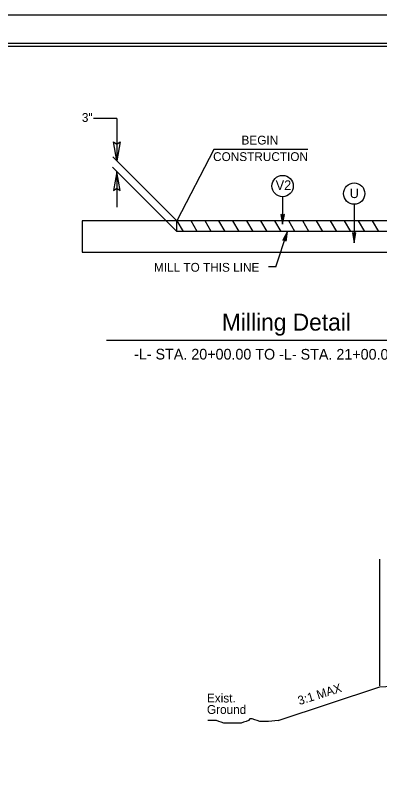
# Model space of a CAD drawing. Extents: x 1497225 to 1499181, y 579958 to 582278.
# Drawn here: x 1497879 to 1498169, y 581678 to 582278 of the extents above; entities that cross this region are included whole.
import ezdxf

# ---------------------------------------------------------------- set-up
doc = ezdxf.new("R2010")
doc.units = 0
for name, color, linetype in [('Default', 7, 'Continuous'), ('Old_Level_1', 7, 'Continuous'), ('Prop Dimension', 7, 'Continuous'), ('Prop Dimension Text', 7, 'Continuous'), ('Prop EOT', 7, 'Continuous'), ('Sheet Cutting Line CELL', 7, 'Continuous'), ('Sheet Plot Border Inside CELL', 7, 'Continuous'), ('Sheet Plot Border Outside CELL', 7, 'Continuous'), ('Sheet Typical CELL', 7, 'Continuous'), ('Typical ID Circle CELL', 7, 'Continuous'), ('Typical Terminator CELL', 7, 'Continuous'), ('Typical Text General CELL', 7, 'Continuous'), ('Typical Text ID Circle CELL', 7, 'Continuous')]:
    doc.layers.add(name, color=color, linetype=linetype)

msp = doc.modelspace()

# ---------------------------------------------------------------- linework, layer by layer
at = {"layer": 'Default'}
for p, q in [((1497959.55, 582195.79), (1497940.95, 582195.79)), ((1497959.55, 582195.79), (1497959.55, 582162.11)), ((1497956.44, 582165.21), (1498007.12, 582114.53)), ((1497956.05, 582157), (1498007.12, 582105.93)), ((1497959.55, 582153.51), (1497959.55, 582125.41))]:
    msp.add_line(p, q, dxfattribs=at)
at = {"layer": 'Old_Level_1'}
for p, q in [((1498036.44, 582171.24), (1498007.12, 582114.53)), ((1498111.16, 582171.24), (1498036.44, 582171.24)), ((1498085.75, 582077.93), (1498095.17, 582105.93)), ((1498085.75, 582077.93), (1498079.88, 582077.93)), ((1497951.27, 582019.56), (1498227.27, 582019.56)), ((1498168.53, 581744.91), (1498168.53, 581845.55)), ((1498168.53, 581744.13), (1498216.42, 581746.79)), ((1498087.75, 581717.2), (1498168.53, 581744.13))]:
    msp.add_line(p, q, dxfattribs=at)
msp.add_lwpolyline([(1498087.75, 581717.2), (1498079.88, 581716.55), (1498077.91, 581716.55), (1498074.96, 581716.55), (1498072.99, 581716.55), (1498071.02, 581717.2), (1498069.06, 581717.86), (1498067.09, 581718.52), (1498065.12, 581718.52), (1498064.14, 581717.2), (1498062.17, 581716.55), (1498060.2, 581715.89), (1498058.24, 581715.24), (1498056.27, 581715.24), (1498054.3, 581715.24), (1498052.34, 581715.24), (1498050.37, 581715.24), (1498048.4, 581715.24), (1498046.44, 581715.24), (1498044.47, 581715.24), (1498042.5, 581715.89), (1498040.54, 581716.55), (1498038.57, 581717.2), (1498035.61, 581717.2), (1498033.65, 581717.2), (1498031.68, 581717.2)], dxfattribs=at)
at = {"layer": 'Prop Dimension'}
msp.add_lwpolyline([(1498285.68, 582114.53), (1497932.02, 582114.53), (1497932.02, 582089.48), (1498279.23, 582089.48)], dxfattribs=at)
at = {"layer": 'Prop EOT'}
for p, q in [((1498285.68, 582114.53), (1498007.12, 582114.53)), ((1498007.12, 582105.93), (1498007.12, 582114.53)), ((1498012.36, 582105.93), (1498007.4, 582114.53)), ((1498023.45, 582105.93), (1498018.48, 582114.53)), ((1498034.53, 582105.93), (1498029.57, 582114.53)), ((1498045.62, 582105.93), (1498040.65, 582114.53)), ((1498056.7, 582105.93), (1498051.74, 582114.53)), ((1498067.79, 582105.93), (1498062.82, 582114.53)), ((1498078.87, 582105.93), (1498073.91, 582114.53)), ((1498089.96, 582105.93), (1498084.99, 582114.53)), ((1498101.04, 582105.93), (1498096.08, 582114.53)), ((1498112.13, 582105.93), (1498107.16, 582114.53)), ((1498123.21, 582105.93), (1498118.25, 582114.53)), ((1498134.3, 582105.93), (1498129.33, 582114.53)), ((1498145.38, 582105.93), (1498140.42, 582114.53)), ((1498156.47, 582105.93), (1498151.5, 582114.53)), ((1498167.55, 582105.93), (1498162.59, 582114.53)), ((1498284.72, 582105.93), (1498007.12, 582105.93))]:
    msp.add_line(p, q, dxfattribs=at)
at = {"layer": 'Sheet Cutting Line CELL'}
msp.add_line((1498909.23, 582277.96), (1497225.23, 582277.96), dxfattribs=at)
at = {"layer": 'Sheet Plot Border Inside CELL'}
msp.add_lwpolyline([(1498904.73, 582255.51), (1497238.23, 582255.51), (1497238.23, 581200.41), (1498904.73, 581200.41)], close=True, dxfattribs=at)
at = {"layer": 'Sheet Plot Border Outside CELL'}
msp.add_lwpolyline([(1498909.23, 582277.96), (1497225.23, 582277.96), (1497225.23, 581177.96), (1498909.23, 581177.96)], close=True, dxfattribs=at)
at = {"layer": 'Sheet Typical CELL'}
msp.add_lwpolyline([(1498892.23, 582252.96), (1497392.23, 582252.96), (1497392.23, 581202.96), (1498892.23, 581202.96)], close=True, dxfattribs=at)
at = {"layer": 'Typical ID Circle CELL'}
for p, q in [((1498091.22, 582133.6), (1498091.22, 582111.73)), ((1498148.09, 582127.64), (1498148.09, 582097.07))]:
    msp.add_line(p, q, dxfattribs=at)
for centre in [(1498091.22, 582142.06), (1498148.09, 582136.1)]:
    msp.add_circle(centre, 8.46, dxfattribs=at)
at = {"layer": 'Typical Terminator CELL'}
for points in [[(1497962.13, 582177.1), (1497959.55, 582162.11), (1497956.88, 582177.19), (1497959.55, 582175.27)], [(1497962.13, 582138.51), (1497959.55, 582153.51), (1497956.88, 582138.43), (1497959.55, 582140.34)], [(1498089.89, 582119.46), (1498091.22, 582111.73), (1498092.6, 582119.51), (1498091.22, 582118.52)], [(1498093.97, 582098.17), (1498095.17, 582105.93), (1498091.39, 582099), (1498093.01, 582099.5)], [(1498146.76, 582104.81), (1498148.09, 582097.07), (1498149.46, 582104.85), (1498148.09, 582103.86)]]:
    msp.add_lwpolyline(points, close=True, dxfattribs=at)

# ---------------------------------------------------------------- texts
at = {"layer": 'Old_Level_1'}
for s, p in [('3"', (1497931.71, 582193.07)), ('MILL TO THIS LINE', (1497988.98, 582073.99))]:
    msp.add_text(s, height=7, dxfattribs=at).set_placement(p)
for s, height, rotation, p in [('-L- STA. 20+00.00 TO -L- STA. 21+00.00', 8.5, 359.94924, (1497973.18, 582004.26)), ('3:1 MAX', 7, 17.44037, (1498104.56, 581729.51)), ('Exist.', 7, 359.94924, (1498031.09, 581731.67)), ('Ground', 7, 359.94924, (1498031.08, 581722.57))]:
    msp.add_text(s, height=height, rotation=rotation, dxfattribs=at).set_placement(p)
at = {"layer": 'Prop Dimension Text'}
for s, p in [('BEGIN', (1498058.57, 582175.09)), ('CONSTRUCTION', (1498035.98, 582161.96))]:
    msp.add_text(s, height=7, rotation=0.00014, dxfattribs=at).set_placement(p)
at = {"layer": 'Typical Text General CELL'}
msp.add_text('Milling Detail', height=13.52, dxfattribs=at).set_placement((1498042.99, 582027.19))
at = {"layer": 'Typical Text ID Circle CELL'}
for s, height, p in [('V2', 7.575, (1498085.69, 582139.03)), ('U', 7.58, (1498144.53, 582132.53))]:
    msp.add_text(s, height=height, dxfattribs=at).set_placement(p)

doc.saveas('drawing.dxf')
